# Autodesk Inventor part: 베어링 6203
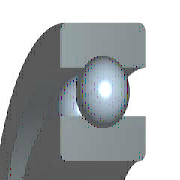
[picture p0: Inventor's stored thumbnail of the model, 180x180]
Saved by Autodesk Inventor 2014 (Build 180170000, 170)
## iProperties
IsCustomPart: 1
Company: 한국ATC센터
Created: 2009-02
Part Number: 베어링 6203
Material: Steel, Mild
Description: 깊은 그루브 볼 베어링
Document SubType Name: Modeling
Standard: KS B 2023
Designer: KYOUNG IL JANG
Standards Organization: KS
Language: ko-KR
Size Designation: 6203 - 17 x 40 x 12
Categories: <MemberInstance><Categories><Category DisplayName="샤프트 부품" InternalName="7f7aeb1f-a693-4053-b835-cee3144e0d98" Mnemonic="SHFT"><Category DisplayName="베어링" Inter
Density: 1 g/cm^3
Appearance: Steel
Author: KYOUNG IL JANG
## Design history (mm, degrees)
revolve "본체" stored, may be unused: angle "d6" = 90 deg
revolve "볼" stored, may be unused: angle "d7" = 90 deg
pattern_circular "IDS_ARRAYBALL[SIMPL:T]" dims angle "d3" = 360 deg
body "Solid1"
sketch "스케치" dims "d0" = 5.98 (= -0.26 x WD + 0.26 x BD)
  geometry: L1 (3.01, 14.25)-(8.99, 14.25); L2 (6, 14.25)-(6, 11.26); L3 (6, 14.25)-(6, 17.24); L4 (3.778, 12.249)-(0, 12.249); L5 (0, 8.5)-(12, 8.5); L6 (3.778, 16.251)-(0, 16.251); L7 (0, 20)-(12, 20); L8 (12, 8.5)-(12, 12.249); L9 (8.222, 12.249)-(12, 12.249); L10 (8.222, 16.251)-(12, 16.251); L11 (12, 20)-(12, 16.251); L12 (-1.4, 0)-(8.4, 0) reference; L13 (0, -0.3)-(0, 5.3) reference
  constraints: 22 end point, 4 point on line, 2 collinear, 2 perpendicular, 2 symmetric about line, 1 midpoint, 1 parallel, 14 other
  dimensions: "d9" = 17 diameter of L5 L12 (= WD); "d11" = 40 diameter of L7 L12 (= BD); "d12" = 12 distance between parallel lines of L8 L13 (= KB); "d13" = 24.498 diameter of L9 L12 (= 0.326 x BD + 0.674 x WD)
fillet "모깎기1" dims "d1" = 0.6 (= KRS)
other parameters: "WD" = 17 [user parameter; used in 5 equation terms], "BD" = 40 [user parameter; used in 5 equation terms], "KB" = 12 [user parameter; used in 1 equation term], "KRS" = 0.6 [user parameter; used in 1 equation term], "d4" = 0, "d5" = 0, "d8" = 0, "d14" = 0, "d15" = 0, "BBA" = 0 [user parameter], "BC0" = 4750000 [user parameter], "BC" = 9560000 [user parameter], "WR" = 8.5 (= 0.5 x WD) [user parameter]
